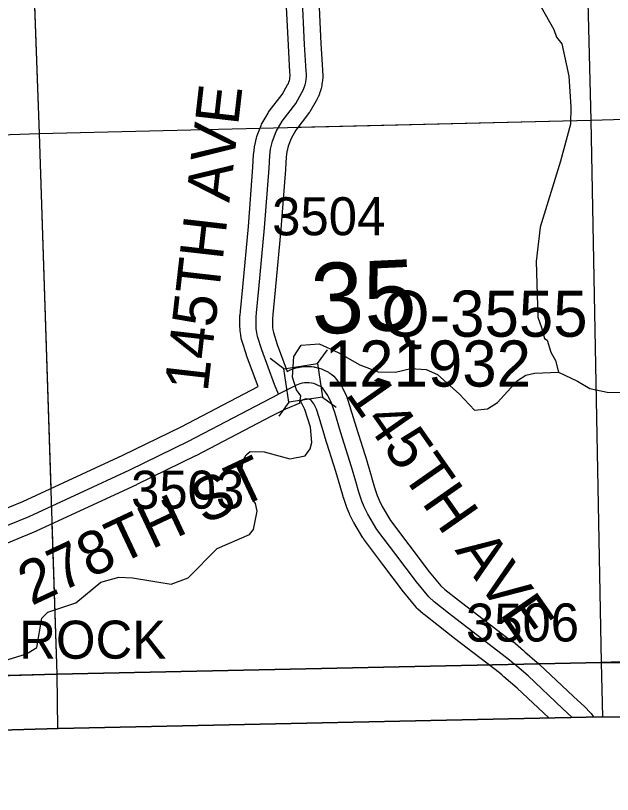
# Model space of a CAD drawing. Extents: x 128.7 to 185.5, y -21.4 to 12.6.
# Drawn here: x 138.263 to 139.361, y -13.823 to -12.39 of the extents above; entities that cross this region are included whole.
import ezdxf

# ---------------------------------------------------------------- set-up
doc = ezdxf.new("R2010")
doc.units = 0
for name, color, linetype in [('tdCoClipBndry', 7, 'Continuous'), ('tdCoCoBndry', 7, 'Continuous'), ('tdCoCoBndryPart', 7, 'Continuous'), ('tdCoHydroRiver', 7, 'Continuous'), ('tdCoSecRdNmbr', 7, 'Continuous'), ('tdCoSecRdTxt', 7, 'Continuous'), ('tdCoSecRteBand', 7, 'Continuous'), ('tdCoSecRteCL', 7, 'Continuous'), ('tdCoSectLine', 7, 'Continuous'), ('tdCoSectLinePart', 7, 'Continuous'), ('tdCoSectNmbr', 7, 'Continuous'), ('tdCoStrucSec', 7, 'Continuous'), ('tdCoStrucSecCoName', 7, 'Continuous'), ('tdCoStrucSecFHWANum', 7, 'Continuous'), ('tdCoSurfGravel', 7, 'Continuous'), ('tdCoTwpBndryShd', 7, 'Continuous'), ('tdCoUnicrpTwnTxt', 7, 'Continuous')]:
    doc.layers.add(name, color=color, linetype=linetype)

msp = doc.modelspace()

# ---------------------------------------------------------------- linework, layer by layer
at = {"layer": 'tdCoClipBndry'}
msp.add_lwpolyline([(140.0473, -13.6827), (139.3409, -13.68), (138.3408, -13.7014), (135.3417, -13.7884), (134.3324, -13.8229), (134.2979, -13.818), (134.2605, -13.7958), (134.2397, -13.7678), (134.2291, -13.7257), (134.1751, -11.7221), (134.1418, -10.7117), (134.1187, -9.7087), (134.0612, -7.7025), (133.8962, -2.6807)], dxfattribs=at)
at = {"layer": 'tdCoCoBndry'}
for p, q in [((140.1254, -13.5551), (139.3404, -13.58)), ((139.3404, -13.58), (140.1254, -13.5551)), ((139.3404, -13.58), (138.3387, -13.6015)), ((138.3387, -13.6015), (139.3404, -13.58)), ((138.3387, -13.6015), (137.3418, -13.6288)), ((137.3418, -13.6288), (138.3387, -13.6015))]:
    msp.add_line(p, q, dxfattribs=at)
for points in [[(140.1254, -13.5551), (139.3404, -13.58), (138.3387, -13.6015), (137.3418, -13.6288), (136.3432, -13.661), (135.3389, -13.6885), (134.3294, -13.723), (134.3001, -12.7212), (134.2754, -11.7191), (134.2421, -10.7094), (134.219, -9.7062), (134.1879, -8.683), (134.1615, -7.6994), (134.1297, -6.7029)], [(140.1254, -13.5551), (139.3404, -13.58), (138.3387, -13.6015), (137.3418, -13.6288), (136.3432, -13.661), (135.3389, -13.6885), (134.3294, -13.723), (134.3318, -13.8228), (134.3324, -13.8229), (135.3417, -13.7884), (138.3408, -13.7014), (139.3409, -13.68), (140.0473, -13.6827)], [(134.329, -13.723), (135.3385, -13.6885), (136.3429, -13.661), (137.3414, -13.6288), (138.3383, -13.6015), (139.34, -13.58), (140.0257, -13.5827)]]:
    msp.add_lwpolyline(points, dxfattribs=at)
at = {"layer": 'tdCoCoBndryPart'}
for points in [[(138.0479, -13.6095), (138.3383, -13.6015), (139.1333, -13.5844)], [(139.2248, -13.5825), (139.34, -13.58), (139.5652, -13.5728)]]:
    msp.add_lwpolyline(points, dxfattribs=at)
at = {"layer": 'tdCoHydroRiver'}
for points in [[(139.2291, -12.3733), (139.2525, -12.4152), (139.2577, -12.4292), (139.2676, -12.4416), (139.2805, -12.5011), (139.2838, -12.5578), (139.2832, -12.5894), (139.2648, -12.6579), (139.2276, -12.779), (139.2201, -12.8423), (139.2233, -12.9448), (139.2302, -12.9635), (139.2356, -12.9839), (139.2404, -12.9869), (139.2474, -13.0088), (139.2558, -13.0243), (139.2612, -13.0462)], [(138.2408, -13.5768), (138.283, -13.5644), (138.3016, -13.5528), (138.311, -13.4988), (138.3217, -13.4875), (138.3732, -13.4701), (138.4194, -13.4323), (138.4523, -13.4234), (138.4775, -13.4242), (138.5489, -13.4362), (138.5801, -13.4242), (138.6337, -13.3704), (138.6929, -13.3449), (138.7004, -13.3352), (138.7073, -13.3018), (138.7037, -13.2877), (138.6971, -13.2785), (138.6782, -13.2301), (138.6822, -13.2063), (138.6867, -13.1983), (138.6944, -13.1917), (138.7197, -13.1925), (138.7674, -13.2052), (138.7956, -13.1996), (138.8047, -13.1867), (138.8075, -13.1756), (138.8051, -13.1473), (138.7946, -13.1144), (138.7861, -13.0973), (138.7875, -13.0894), (138.7792, -13.0786), (138.7722, -13.0552), (138.7742, -13.0172), (138.7877, -12.9963), (138.8208, -12.9937), (138.856, -13.0099), (138.8962, -13.0324), (138.9297, -13.0455), (138.9613, -13.0461), (138.9895, -13.0389), (139.018, -13.0412), (139.0388, -13.05), (139.0794, -13.0866), (139.1071, -13.1157), (139.1307, -13.1134), (139.1493, -13.1018), (139.1859, -13.0612), (139.2014, -13.0512), (139.217, -13.0476), (139.2612, -13.0462), (139.2964, -13.0625), (139.3189, -13.076), (139.3507, -13.0829), (139.3933, -13.0831)]]:
    msp.add_lwpolyline(points, dxfattribs=at)
at = {"layer": 'tdCoSecRteBand'}
for points in [[(138.2034, -13.3134), (138.2759, -13.2839), (138.4597, -13.1987), (138.5671, -13.1462), (138.7086, -13.0722), (138.6876, -13.0152), (138.6874, -13.0146), (138.6872, -13.014), (138.6793, -12.9893), (138.6788, -12.9876), (138.6784, -12.9859), (138.677, -12.9788), (138.6769, -12.9779), (138.6768, -12.977), (138.6758, -12.9698), (138.6757, -12.9689), (138.6756, -12.968), (138.6751, -12.9608), (138.6751, -12.9599), (138.675, -12.959), (138.675, -12.9517), (138.675, -12.9508), (138.675, -12.9499), (138.6754, -12.9427), (138.6754, -12.9418), (138.6755, -12.9409), (138.6763, -12.9339), (138.6805, -12.8896), (138.6908, -12.7779), (138.6991, -12.6688), (138.7004, -12.6455), (138.7004, -12.6443), (138.7006, -12.6432), (138.702, -12.6316), (138.7022, -12.6302), (138.7025, -12.6289), (138.7057, -12.6146), (138.7062, -12.6123), (138.7071, -12.6102), (138.7142, -12.5919), (138.715, -12.5898), (138.7162, -12.5878), (138.727, -12.5691), (138.728, -12.5674), (138.7292, -12.5659), (138.7529, -12.5349), (138.7631, -12.5173), (138.7645, -12.5146), (138.7655, -12.512), (138.7664, -12.5094), (138.767, -12.5067), (138.7674, -12.504), (138.7676, -12.5012), (138.7676, -12.4984), (138.7673, -12.4945), (138.7672, -12.494), (138.7672, -12.4936), (138.7645, -12.4445), (138.7645, -12.4444), (138.7645, -12.4442), (138.76, -12.3505)], [(138.82, -12.3479), (138.8244, -12.4413), (138.8271, -12.4898), (138.8275, -12.4944), (138.8276, -12.4956), (138.8276, -12.4968), (138.8276, -12.5019), (138.8276, -12.5031), (138.8276, -12.5043), (138.8272, -12.5094), (138.8271, -12.5106), (138.8269, -12.5118), (138.8262, -12.5169), (138.826, -12.518), (138.8257, -12.5192), (138.8245, -12.5242), (138.8243, -12.5254), (138.8239, -12.5265), (138.8223, -12.5314), (138.822, -12.5325), (138.8215, -12.5336), (138.8196, -12.5384), (138.8191, -12.5395), (138.8186, -12.5405), (138.8163, -12.5451), (138.8159, -12.5459), (138.8154, -12.5467), (138.8039, -12.5666), (138.8029, -12.5683), (138.8017, -12.5698), (138.778, -12.6008), (138.7693, -12.6159), (138.7638, -12.6299), (138.7614, -12.6406), (138.7602, -12.6497), (138.759, -12.6722), (138.759, -12.6726), (138.759, -12.673), (138.7506, -12.7827), (138.7506, -12.7829), (138.7506, -12.7832), (138.7402, -12.8951), (138.7402, -12.8952), (138.7402, -12.8952), (138.736, -12.9398), (138.736, -12.9401), (138.736, -12.9404), (138.7353, -12.9466), (138.735, -12.9521), (138.735, -12.9575), (138.7354, -12.9629), (138.7361, -12.9683), (138.737, -12.9727), (138.7441, -12.9951), (138.7624, -13.0446), (138.7656, -13.0429), (138.7668, -13.0423), (138.768, -13.0418), (138.7742, -13.0394), (138.7761, -13.0386), (138.778, -13.0381), (138.7823, -13.0371), (138.7837, -13.0367), (138.7851, -13.0365), (138.7894, -13.0358), (138.7908, -13.0356), (138.7923, -13.0356), (138.7967, -13.0353), (138.7981, -13.0352), (138.7995, -13.0353), (138.8039, -13.0355), (138.8053, -13.0355), (138.8067, -13.0357), (138.8111, -13.0363), (138.8125, -13.0365), (138.8139, -13.0368), (138.8182, -13.0378), (138.8195, -13.0381), (138.8209, -13.0386), (138.8251, -13.04), (138.8264, -13.0404), (138.8277, -13.041), (138.8317, -13.0428), (138.833, -13.0434), (138.8343, -13.0441), (138.8381, -13.0462), (138.8393, -13.0469), (138.8405, -13.0477), (138.8441, -13.0502), (138.8482, -13.0531), (138.8511, -13.0571), (138.8615, -13.0711), (138.8632, -13.0735), (138.8645, -13.0761), (138.8711, -13.0901), (138.8719, -13.0918), (138.8725, -13.0936), (138.8782, -13.1109), (138.8783, -13.1113), (138.8784, -13.1117), (138.889, -13.147), (138.9091, -13.2109), (138.9092, -13.2111), (138.9093, -13.2113), (138.9174, -13.2387), (138.9175, -13.239), (138.9175, -13.2392), (138.9227, -13.2579), (138.9279, -13.2731), (138.9313, -13.2815), (138.9369, -13.2928), (138.9523, -13.3186), (138.9861, -13.3636), (139.0237, -13.4132), (139.0446, -13.4388), (139.052, -13.4455), (139.0775, -13.4656), (139.1067, -13.4884), (139.1766, -13.5419), (139.1773, -13.5411), (139.1972, -13.5583), (139.1997, -13.5604), (139.2224, -13.58), (139.2249, -13.5821), (139.2254, -13.5826), (139.2259, -13.583), (139.2892, -13.6429), (139.3098, -13.662), (139.3104, -13.6625), (139.3109, -13.6631), (139.3186, -13.671), (139.32, -13.6725), (139.3212, -13.6742), (139.3257, -13.6803)], [(139.2433, -13.6821), (139.1852, -13.6271), (139.1609, -13.6062), (139.158, -13.6037), (139.1526, -13.599), (139.0701, -13.5359), (139.07, -13.5358), (139.0699, -13.5357), (139.0406, -13.5128), (139.0405, -13.5128), (139.0405, -13.5128), (139.0141, -13.4921), (139.0133, -13.4914), (139.0126, -13.4908), (139.0027, -13.4819), (139.001, -13.4803), (138.9995, -13.4785), (138.9768, -13.4507), (138.9765, -13.4503), (138.9762, -13.4498), (138.9382, -13.3998), (138.9382, -13.3997), (138.9381, -13.3997), (138.9034, -13.3533), (138.9024, -13.352), (138.9016, -13.3507), (138.8848, -13.3225), (138.8842, -13.3216), (138.8837, -13.3206), (138.8771, -13.3073), (138.8766, -13.3062), (138.8761, -13.3051), (138.8719, -13.2948), (138.8716, -13.2939), (138.8713, -13.2931), (138.8656, -13.2763), (138.8654, -13.2756), (138.8652, -13.2748), (138.8598, -13.2556), (138.8518, -13.2287), (138.8317, -13.1648), (138.8316, -13.1646), (138.8315, -13.1643), (138.821, -13.1292), (138.8161, -13.1141), (138.8115, -13.1044), (138.806, -13.097), (138.8046, -13.0964), (138.8032, -13.0959), (138.8016, -13.0956), (138.8001, -13.0954), (138.7986, -13.0953), (138.797, -13.0954), (138.7955, -13.0956), (138.7946, -13.0958), (138.7915, -13.0971), (138.7843, -13.1007), (138.7853, -13.1031), (138.7589, -13.1137), (138.7336, -13.1269), (138.5945, -13.1996), (138.5942, -13.1998), (138.5938, -13.2), (138.4858, -13.2528), (138.4855, -13.2529), (138.4852, -13.253), (138.3005, -13.3386), (138.2999, -13.3389), (138.2992, -13.3392), (138.226, -13.369)]]:
    msp.add_lwpolyline(points, dxfattribs=at)
at = {"layer": 'tdCoSecRteCL'}
for points in [[(138.7463, -13.0864), (138.7392, -13.0685), (138.7158, -13.0048), (138.7079, -12.9802), (138.7065, -12.9731), (138.7055, -12.9659), (138.705, -12.9587), (138.705, -12.9514), (138.7053, -12.9442), (138.7061, -12.937), (138.7103, -12.8924), (138.7207, -12.7804), (138.7291, -12.6707), (138.7303, -12.647), (138.7318, -12.6354), (138.735, -12.6211), (138.7421, -12.6029), (138.753, -12.5841), (138.7779, -12.5516), (138.7895, -12.5316), (138.7918, -12.527), (138.7938, -12.5223), (138.7953, -12.5174), (138.7965, -12.5124), (138.7973, -12.5073), (138.7976, -12.5022), (138.7976, -12.497), (138.7971, -12.4919), (138.7944, -12.4428), (138.79, -12.3491)], [(139.1801, -13.5831), (139.1715, -13.5757), (139.0884, -13.5121), (139.059, -13.4892), (139.0327, -13.4685), (139.0228, -13.4596), (139.0001, -13.4317), (138.9621, -13.3817), (138.9274, -13.3353), (138.9106, -13.3072), (138.9039, -13.2939), (138.8997, -13.2835), (138.8941, -13.2667), (138.8886, -13.2473), (138.8805, -13.2199), (138.8603, -13.1558), (138.8497, -13.1202), (138.844, -13.103), (138.8373, -13.0889), (138.827, -13.0749), (138.8234, -13.0724), (138.8195, -13.0702), (138.8155, -13.0684), (138.8113, -13.067), (138.8071, -13.066), (138.8027, -13.0654), (138.7983, -13.0653), (138.7939, -13.0655), (138.7896, -13.0662), (138.7853, -13.0672), (138.7791, -13.0697), (138.7476, -13.0857), (138.7463, -13.0864)], [(137.97, -13.4375), (138.0124, -13.4214), (138.1121, -13.3821), (138.2147, -13.3412), (138.2879, -13.3114), (138.4726, -13.2258), (138.5806, -13.173), (138.7463, -13.0864)], [(139.2863, -13.6811), (139.2687, -13.6648), (139.2053, -13.6048), (139.1804, -13.5834)]]:
    msp.add_lwpolyline(points, dxfattribs=at)
at = {"layer": 'tdCoSectLine'}
for points in [[(139.2948, -11.5676), (139.3211, -12.5822)], [(138.2688, -11.5873), (138.3061, -12.6068)], [(139.3211, -12.5822), (140.3203, -12.5525)], [(138.3061, -12.6068), (139.3211, -12.5822)], [(139.3211, -12.5822), (139.34, -13.58)], [(137.2924, -12.6416), (138.3061, -12.6068)], [(138.3061, -12.6068), (138.3383, -13.6015)], [(139.34, -13.58), (140.3446, -13.5481)], [(138.3383, -13.6015), (139.34, -13.58)], [(139.34, -13.58), (139.3425, -13.68)], [(137.3414, -13.6288), (138.3383, -13.6015)], [(138.3383, -13.6015), (138.3396, -13.7015)]]:
    msp.add_lwpolyline(points, dxfattribs=at)
at = {"layer": 'tdCoSectLinePart'}
for points in [[(139.2948, -11.5676), (139.3211, -12.5822)], [(138.271, -11.6468), (138.3061, -12.6068)], [(139.3211, -12.5822), (140.3203, -12.5525)], [(138.7818, -12.5953), (139.3211, -12.5822)], [(139.3211, -12.5822), (139.34, -13.58)], [(138.3061, -12.6068), (138.712, -12.597)], [(137.8456, -12.6226), (138.3061, -12.6068)], [(138.3061, -12.6068), (138.3273, -13.2599)], [(138.3294, -13.325), (138.3383, -13.6015)], [(138.3383, -13.6015), (139.1333, -13.5844)], [(139.2248, -13.5825), (139.34, -13.58)], [(139.34, -13.58), (139.5652, -13.5728)], [(139.34, -13.58), (139.3425, -13.68)], [(138.0479, -13.6095), (138.3383, -13.6015)], [(138.3383, -13.6015), (138.3396, -13.7015)]]:
    msp.add_lwpolyline(points, dxfattribs=at)
at = {"layer": 'tdCoStrucSec'}
for p, q in [((138.8178, -13.0302), (138.8364, -13.005)), ((138.7559, -13.0395), (138.7307, -13.021)), ((138.8272, -13.0921), (138.8524, -13.1106)), ((138.7653, -13.1014), (138.7467, -13.1266))]:
    msp.add_line(p, q, dxfattribs=at)
msp.add_lwpolyline([(138.8272, -13.0921), (138.7653, -13.1014), (138.7559, -13.0395), (138.8178, -13.0302)], close=True, dxfattribs=at)
at = {"layer": 'tdCoSurfGravel'}
for points in [[(139.1801, -13.5831), (139.1715, -13.5757), (139.0884, -13.5121), (139.059, -13.4892), (139.0327, -13.4685), (139.0228, -13.4596), (139.0001, -13.4317), (138.9621, -13.3817), (138.9274, -13.3353), (138.9106, -13.3072), (138.9039, -13.2939), (138.8997, -13.2835), (138.8941, -13.2667), (138.8886, -13.2473), (138.8805, -13.2199), (138.8603, -13.1558), (138.8497, -13.1202), (138.844, -13.103), (138.8373, -13.0889), (138.827, -13.0749), (138.8234, -13.0724), (138.8195, -13.0702), (138.8155, -13.0684), (138.8113, -13.067), (138.8071, -13.066), (138.8027, -13.0654), (138.7983, -13.0653), (138.7939, -13.0655), (138.7896, -13.0662), (138.7853, -13.0672), (138.7791, -13.0697), (138.7476, -13.0857), (138.7463, -13.0864), (138.7392, -13.0685), (138.7158, -13.0048), (138.7079, -12.9802), (138.7065, -12.9731), (138.7055, -12.9659), (138.705, -12.9587), (138.705, -12.9514), (138.7053, -12.9442), (138.7061, -12.937), (138.7103, -12.8924), (138.7207, -12.7804), (138.7291, -12.6707), (138.7303, -12.647), (138.7318, -12.6354), (138.735, -12.6211), (138.7421, -12.6029), (138.753, -12.5841), (138.7779, -12.5516), (138.7895, -12.5316), (138.7918, -12.527), (138.7938, -12.5223), (138.7953, -12.5174), (138.7965, -12.5124), (138.7973, -12.5073), (138.7976, -12.5022), (138.7976, -12.497), (138.7971, -12.4919), (138.7944, -12.4428), (138.79, -12.3491)], [(137.97, -13.4375), (138.0124, -13.4214), (138.1121, -13.3821), (138.2147, -13.3412), (138.2879, -13.3114), (138.4726, -13.2258), (138.5806, -13.173), (138.7463, -13.0864)], [(139.2863, -13.6811), (139.2687, -13.6648), (139.2053, -13.6048), (139.1804, -13.5834)]]:
    msp.add_lwpolyline(points, dxfattribs=at)
at = {"layer": 'tdCoTwpBndryShd'}
msp.add_lwpolyline([(134.1293, -6.7029), (134.1612, -7.6994), (134.1875, -8.683), (134.2186, -9.7062), (134.2417, -10.7094), (134.275, -11.7191), (134.2997, -12.7212), (134.329, -13.723), (135.3385, -13.6885), (136.3429, -13.661), (137.3414, -13.6288), (138.3383, -13.6015), (139.34, -13.58), (139.5652, -13.5728)], dxfattribs=at)

# ---------------------------------------------------------------- texts
at = {"layer": 'tdCoSecRdNmbr'}
for s, rotation, p in [('3504', 0.1052, (138.7346, -12.7942)), ('3503', 0.105, (138.4751, -13.2973)), ('3506', 0.1054, (139.0911, -13.5418))]:
    msp.add_text(s, height=0.07, rotation=rotation, dxfattribs=at).set_placement(p)
at = {"layer": 'tdCoSecRdTxt'}
for s, rotation, p in [('145TH AVE', 83.4767, (138.6159, -13.0835)), ('145TH AVE', 304.9991, (138.8686, -13.0862)), ('278TH ST', 25.1709, (138.2919, -13.4763))]:
    msp.add_text(s, height=0.08, rotation=rotation, dxfattribs=at).set_placement(p)
at = {"layer": 'tdCoSectNmbr'}
msp.add_text('35', height=0.13, rotation=2.6576, dxfattribs=at).set_placement((138.809, -12.9764))
at = {"layer": 'tdCoStrucSecCoName'}
msp.add_text('Q-3555', height=0.085, dxfattribs=at).set_placement((138.9357, -12.9807))
at = {"layer": 'tdCoStrucSecFHWANum'}
msp.add_text('121932', height=0.085, dxfattribs=at).set_placement((138.8315, -13.0725))
at = {"layer": 'tdCoUnicrpTwnTxt'}
msp.add_text('BIG ROCK', height=0.07, rotation=0.104, dxfattribs=at).set_placement((138.0821, -13.5737))

doc.saveas('drawing.dxf')
